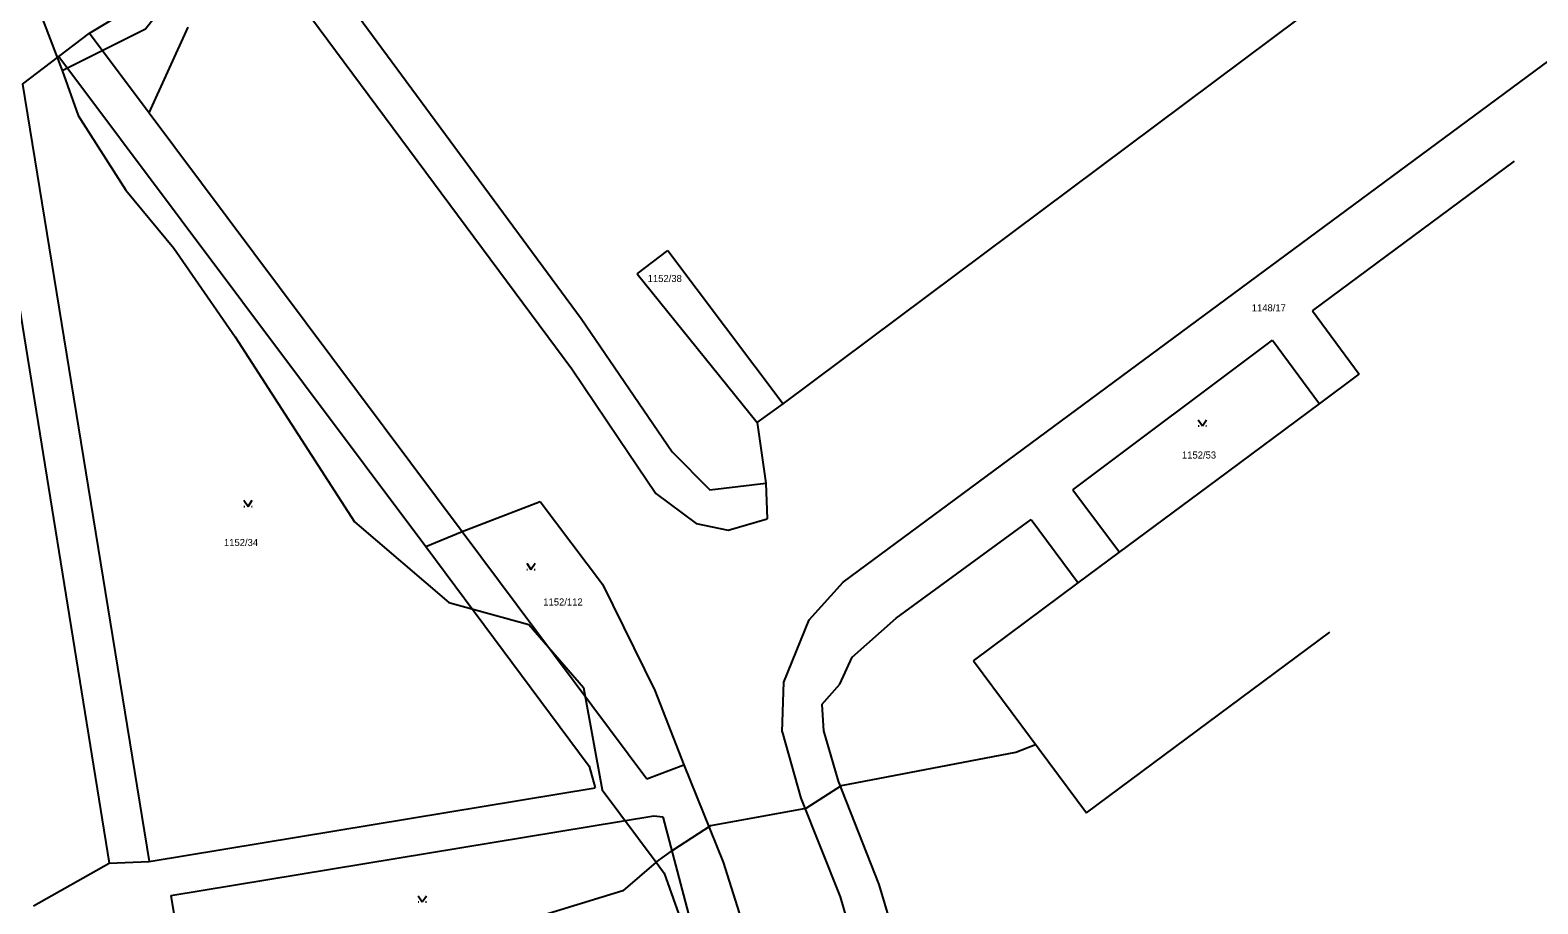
# Model space of a CAD drawing. Extents: x -609709 to -609357, y -1051535 to -1051131.
# Drawn here: x -609496.9 to -609406.2, y -1051300.6 to -1051248 of the extents above; entities that cross this region are included whole.
import ezdxf

# ---------------------------------------------------------------- set-up
doc = ezdxf.new("R2010")
doc.units = 0
doc.layers.add('Vrstva 10', color=7, linetype='Continuous')
doc.layers.add('Vrstva 15', color=7, linetype='Continuous')

msp = doc.modelspace()

# ---------------------------------------------------------------- linework, layer by layer
at = {"layer": 'Vrstva 10'}
for p, q in [((-609451.61, -1051270.48), (-609393.4, -1051226.96)), ((-609448, -1051281.21), (-609386.86, -1051236.01)), ((-609483.09, -1051239.11), (-609463.77, -1051265.35)), ((-609482.39, -1051244.03), (-609464.32, -1051268.37)), ((-609493.34, -1051248.18), (-609489.67, -1051245.95)), ((-609495.18, -1051249.58), (-609493.34, -1051248.18)), ((-609493.34, -1051248.18), (-609489.74, -1051252.97)), ((-609489.74, -1051252.97), (-609487.4, -1051247.82)), ((-609497.36, -1051251.24), (-609495.18, -1051249.58)), ((-609495.18, -1051249.58), (-609473.11, -1051279.05)), ((-609497.36, -1051251.24), (-609489.75, -1051298)), ((-609489.74, -1051252.97), (-609470.91, -1051278.16)), ((-609419.77, -1051264.89), (-609407.61, -1051255.89)), ((-609498.31, -1051259.99), (-609492.16, -1051298.11)), ((-609460.39, -1051262.66), (-609458.55, -1051261.25)), ((-609458.55, -1051261.25), (-609451.61, -1051270.48)), ((-609460.39, -1051262.66), (-609453.18, -1051271.6)), ((-609463.77, -1051265.35), (-609458.29, -1051273.37)), ((-609419.77, -1051264.89), (-609416.95, -1051268.69)), ((-609434.18, -1051275.65), (-609422.18, -1051266.65)), ((-609422.18, -1051266.65), (-609419.35, -1051270.47)), ((-609464.32, -1051268.37), (-609461.51, -1051272.55)), ((-609419.35, -1051270.47), (-609416.95, -1051268.69)), ((-609453.18, -1051271.6), (-609451.61, -1051270.48)), ((-609425.5, -1051275.04), (-609419.35, -1051270.47)), ((-609453.18, -1051271.6), (-609452.66, -1051275.24)), ((-609426.64, -1051271.435), (-609426.39, -1051271.81)), ((-609426.64, -1051271.81), (-609426.59, -1051271.81)), ((-609426.39, -1051271.81), (-609426.14, -1051271.435)), ((-609426.19, -1051271.81), (-609426.14, -1051271.81)), ((-609461.51, -1051272.55), (-609459.26, -1051275.87)), ((-609458.29, -1051273.37), (-609456.02, -1051275.66)), ((-609456.02, -1051275.66), (-609452.66, -1051275.24)), ((-609452.66, -1051275.24), (-609452.58, -1051277.39)), ((-609431.38, -1051279.41), (-609425.5, -1051275.04)), ((-609484.05, -1051276.275), (-609483.8, -1051276.65)), ((-609483.8, -1051276.65), (-609483.55, -1051276.275)), ((-609470.91, -1051278.16), (-609466.22, -1051276.35)), ((-609466.22, -1051276.35), (-609462.47, -1051281.32)), ((-609459.26, -1051275.87), (-609456.84, -1051277.68)), ((-609434.18, -1051275.65), (-609431.38, -1051279.41)), ((-609484.05, -1051276.65), (-609484, -1051276.65)), ((-609483.6, -1051276.65), (-609483.55, -1051276.65)), ((-609473.11, -1051279.05), (-609470.91, -1051278.16)), ((-609470.91, -1051278.16), (-609459.81, -1051293.03)), ((-609456.84, -1051277.68), (-609454.92, -1051278.07)), ((-609454.92, -1051278.07), (-609452.58, -1051277.39)), ((-609444.82, -1051283.38), (-609436.7, -1051277.43)), ((-609436.7, -1051277.43), (-609433.86, -1051281.25)), ((-609473.11, -1051279.05), (-609463.28, -1051292.27)), ((-609467.03, -1051280.065), (-609466.78, -1051280.44)), ((-609466.78, -1051280.44), (-609466.53, -1051280.065)), ((-609433.86, -1051281.25), (-609431.38, -1051279.41)), ((-609467.03, -1051280.44), (-609466.98, -1051280.44)), ((-609466.58, -1051280.44), (-609466.53, -1051280.44)), ((-609462.47, -1051281.32), (-609459.32, -1051287.72)), ((-609450.04, -1051283.48), (-609448, -1051281.21)), ((-609440.16, -1051285.94), (-609433.86, -1051281.25)), ((-609451.57, -1051287.22), (-609450.04, -1051283.48)), ((-609447.45, -1051285.72), (-609444.82, -1051283.38)), ((-609433.37, -1051295.08), (-609418.73, -1051284.21)), ((-609448.21, -1051287.34), (-609447.45, -1051285.72)), ((-609440.16, -1051285.94), (-609433.37, -1051295.08)), ((-609451.66, -1051290.2), (-609451.57, -1051287.22)), ((-609459.32, -1051287.72), (-609457.58, -1051292.2)), ((-609449.28, -1051288.57), (-609448.21, -1051287.34)), ((-609449.28, -1051288.57), (-609449.19, -1051290.15)), ((-609451.66, -1051290.2), (-609450.55, -1051294.19)), ((-609449.19, -1051290.15), (-609448.31, -1051293.18)), ((-609463.28, -1051292.27), (-609462.91, -1051293.57)), ((-609459.81, -1051293.03), (-609457.58, -1051292.2)), ((-609457.58, -1051292.2), (-609455.21, -1051298.05)), ((-609489.75, -1051298), (-609462.91, -1051293.57)), ((-609448.31, -1051293.18), (-609445.86, -1051299.39)), ((-609450.55, -1051294.19), (-609448.19, -1051300.13)), ((-609488.45, -1051300.05), (-609459.39, -1051295.26)), ((-609459.39, -1051295.26), (-609458.85, -1051295.32)), ((-609458.85, -1051295.32), (-609456.45, -1051304.37)), ((-609496.71, -1051300.67), (-609492.16, -1051298.11)), ((-609492.16, -1051298.11), (-609489.75, -1051298)), ((-609455.21, -1051298.05), (-609451.89, -1051308.61)), ((-609445.86, -1051299.39), (-609444.32, -1051304.46)), ((-609488.45, -1051300.05), (-609485.89, -1051315.79)), ((-609473.57, -1051300.065), (-609473.32, -1051300.44)), ((-609473.57, -1051300.44), (-609473.52, -1051300.44)), ((-609473.32, -1051300.44), (-609473.07, -1051300.065)), ((-609473.12, -1051300.44), (-609473.07, -1051300.44)), ((-609448.19, -1051300.13), (-609446.56, -1051305.59))]:
    msp.add_line(p, q, dxfattribs=at)
at = {"layer": 'Vrstva 15'}
for points in [[(-609521.08, -1051202.07), (-609519.34, -1051204.67), (-609514.81, -1051210.66), (-609514.03, -1051211.19), (-609512.3, -1051214.35), (-609507.99, -1051219.96), (-609504.74, -1051225.1), (-609501.77, -1051230.87), (-609499.14, -1051236.87), (-609498.5, -1051240.32), (-609497.15, -1051244.76), (-609494.99, -1051250.43), (-609489.96, -1051247.93), (-609488.37, -1051245.86), (-609482.36, -1051244.46), (-609480.27, -1051243.11), (-609478.75, -1051243.5), (-609475.39, -1051242.82), (-609472.143, -1051242.924)], [(-609494.99, -1051250.43), (-609494.01, -1051253.14), (-609491.16, -1051257.62), (-609488.26, -1051261.12), (-609484.58, -1051266.44), (-609477.4, -1051277.58), (-609471.72, -1051282.43), (-609466.9, -1051283.75), (-609463.63, -1051287.54), (-609462.49, -1051293.69), (-609459.257, -1051298.042), (-609461.25, -1051299.78), (-609466.49, -1051301.38), (-609471.47, -1051302.65), (-609472.4, -1051304.8), (-609473.562, -1051306.057)], [(-609459.257, -1051298.042), (-609458.25, -1051297.33), (-609455.96, -1051295.84), (-609450.23, -1051294.79), (-609448.11, -1051293.43), (-609437.62, -1051291.43), (-609436.421, -1051290.961)], [(-609459.257, -1051298.042), (-609458.77, -1051298.7), (-609456.82, -1051304.18)]]:
    msp.add_lwpolyline(points, dxfattribs=at)

# ---------------------------------------------------------------- texts
at = {"layer": 'Vrstva 10'}
for s, p in [('1152/38', (-609459.76, -1051263.15)), ('1148/17', (-609423.42, -1051264.915)), ('1152/53', (-609427.62, -1051273.77)), ('1152/34', (-609485.25, -1051279.03)), ('1152/112', (-609466.04, -1051282.61))]:
    msp.add_text(s, height=0.425, dxfattribs=at).set_placement(p)

doc.saveas('drawing.dxf')
